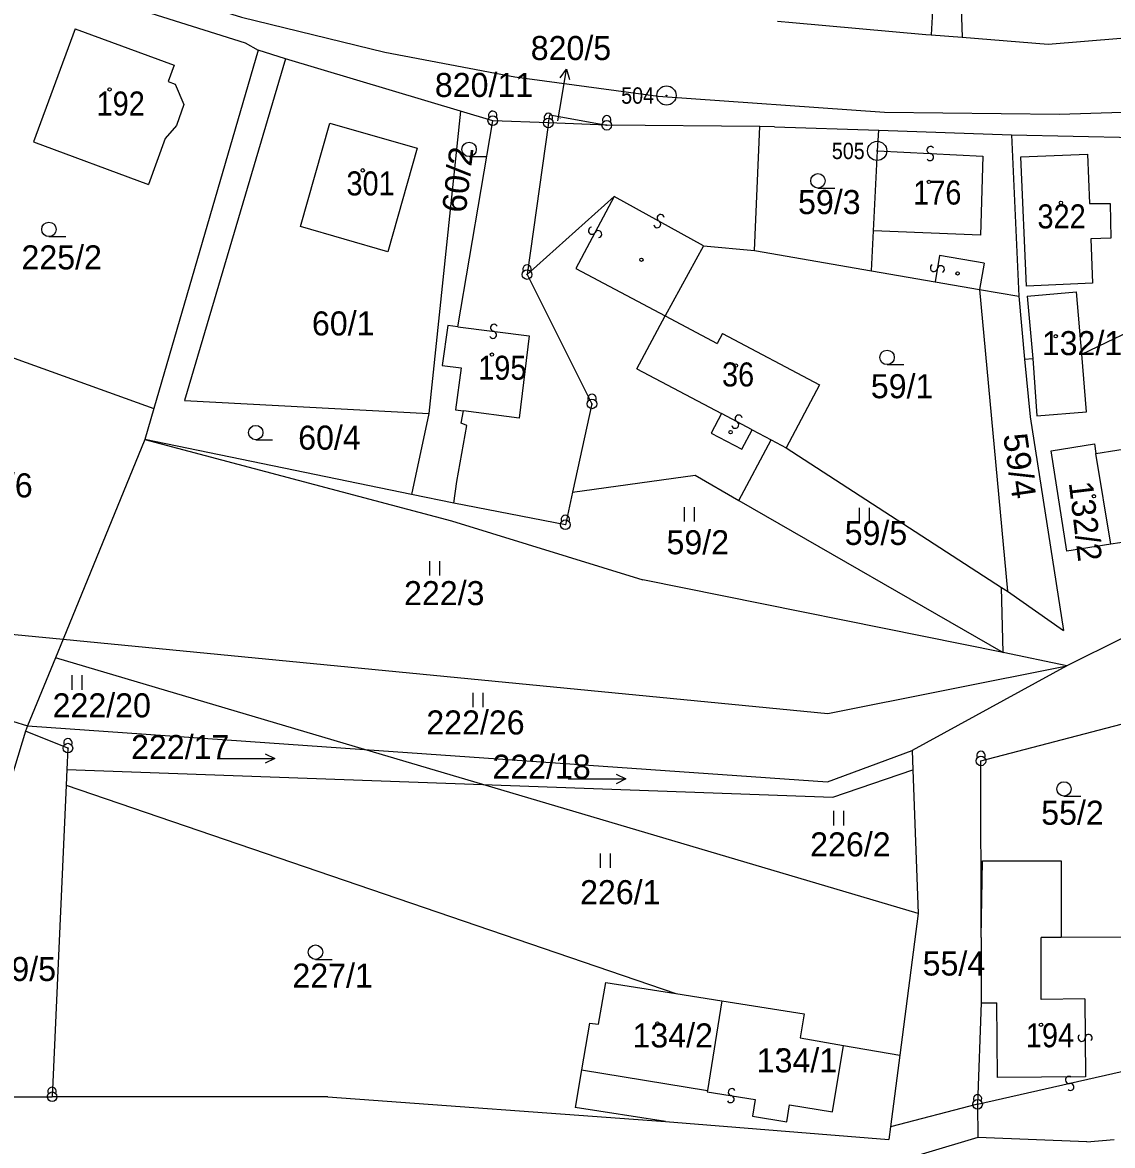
# Model space of a CAD drawing. Extents: x -680102 to -677253, y -1007548 to -1006096.
# Drawn here: x -679953.4 to -679840, y -1007209.6 to -1007092.8 of the extents above; entities that cross this region are included whole.
import ezdxf
from ezdxf.enums import TextEntityAlignment as Align

# ---------------------------------------------------------------- set-up
doc = ezdxf.new("R2010")
doc.units = 0
for name, color, linetype, lineweight in [('1', 7, 'Continuous', 25), ('16', 7, 'Continuous', 25), ('24', 7, 'Continuous', 25), ('25', 7, 'Continuous', 25), ('4', 7, 'Continuous', 25)]:
    doc.layers.add(name, color=color, linetype=linetype, lineweight=lineweight)
for name, color, linetype in [('17', 7, 'Continuous'), ('18', 7, 'Continuous'), ('19', 7, 'Continuous')]:
    doc.layers.add(name, color=color, linetype=linetype)

msp = doc.modelspace()

# ---------------------------------------------------------------- linework, layer by layer
at = {"layer": '1'}
for p, q in [((-679858.64, -1007090.34), (-679858.85, -1007094.13)), ((-679855.79, -1007089.38), (-679855.63, -1007094.38)), ((-679859.4, -1007094.09), (-679858.85, -1007094.13)), ((-679925.99, -1007096.64), (-679928.84, -1007095.74)), ((-679907.8, -1007102.06), (-679925.99, -1007096.64)), ((-679908.09, -1007124.48), (-679904.44, -1007103.06)), ((-679892.58, -1007103.53), (-679898.66, -1007103.29)), ((-679877.23, -1007116.56), (-679876.68, -1007103.67)), ((-679864.41, -1007106.19), (-679864.3, -1007104.05)), ((-679864.84, -1007114.51), (-679864.41, -1007106.19)), ((-679865.06, -1007118.66), (-679864.84, -1007114.51)), ((-679882.51, -1007116.07), (-679877.23, -1007116.56)), ((-679877.23, -1007116.56), (-679865.06, -1007118.66)), ((-679853.8, -1007120.61), (-679849.74, -1007121.31)), ((-679848.86, -1007121.31), (-679843.74, -1007120.86)), ((-679965.95, -1007123.53), (-679939.69, -1007132.98)), ((-679908.09, -1007124.48), (-679909.11, -1007124.34)), ((-679880.54, -1007125.2), (-679881.09, -1007126.23)), ((-679849.12, -1007127.86), (-679848.28, -1007127.79)), ((-679849.12, -1007127.86), (-679848.56, -1007133.84)), ((-679907.73, -1007134.52), (-679907.5, -1007133.24)), ((-679848.56, -1007133.84), (-679845.09, -1007156.09)), ((-679940.63, -1007136.2), (-679908.73, -1007144.68)), ((-679875.49, -1007136.24), (-679873.92, -1007137.07)), ((-679846.36, -1007137.38), (-679841.87, -1007136.68)), ((-679841.87, -1007136.68), (-679841.72, -1007137.67)), ((-679873.92, -1007137.07), (-679851.52, -1007151.59)), ((-679844.74, -1007147.82), (-679846.36, -1007137.38)), ((-679840.16, -1007147.11), (-679841.72, -1007137.67)), ((-679896.14, -1007141.7), (-679883.4, -1007139.91)), ((-679908.73, -1007144.68), (-679888.84, -1007150.8)), ((-679840.16, -1007147.11), (-679844.74, -1007147.82)), ((-679838.89, -1007156.83), (-679844.73, -1007159.74)), ((-679979.45, -1007157.58), (-679952.82, -1007166)), ((-679949.92, -1007158.91), (-679952.82, -1007166)), ((-679917.79, -1007168.44), (-679949.92, -1007158.91)), ((-679844.73, -1007159.74), (-679851.34, -1007158.37)), ((-679844.73, -1007159.74), (-679860.82, -1007168.55)), ((-679952.82, -1007166), (-679953.04, -1007166.53)), ((-679952.82, -1007166), (-679917.79, -1007168.44)), ((-679948.63, -1007168.31), (-679953.04, -1007166.53)), ((-679917.79, -1007168.44), (-679869.61, -1007171.8)), ((-679869.61, -1007171.8), (-679860.82, -1007168.55)), ((-679869.07, -1007173.41), (-679860.75, -1007170.55)), ((-679948.8, -1007172.16), (-679950.27, -1007204.57)), ((-679948.8, -1007172.16), (-679885.41, -1007193.82)), ((-679836.13, -1007187.98), (-679845.34, -1007188)), ((-679880.63, -1007194.58), (-679882.12, -1007203.93)), ((-679894.38, -1007196.9), (-679895.2, -1007201.78)), ((-679872.47, -1007198.45), (-679867.97, -1007199.23)), ((-679867.97, -1007199.23), (-679862.1, -1007200.25)), ((-679895.2, -1007201.78), (-679895.86, -1007205.7)), ((-679895.2, -1007201.78), (-679882.12, -1007203.93)), ((-679964.56, -1007204.56), (-679950.27, -1007204.57)), ((-679921.6, -1007204.59), (-679950.27, -1007204.57)), ((-679921.6, -1007204.59), (-679886.46, -1007207.15)), ((-679886.46, -1007207.15), (-679895.86, -1007205.7)), ((-679854.02, -1007205.35), (-679863.06, -1007207.69)), ((-679854.02, -1007205.35), (-679853.99, -1007208.8)), ((-679886.46, -1007207.15), (-679863.25, -1007209)), ((-679863.06, -1007207.69), (-679863.25, -1007209)), ((-679853.99, -1007208.8), (-679865.24, -1007212.16)), ((-679842.65, -1007209.24), (-679853.99, -1007208.8)), ((-679842.65, -1007209.24), (-679839.8, -1007209.02))]:
    msp.add_line(p, q, dxfattribs=at)
for points in [[(-679974.97, -1007077.43), (-679941.96, -1007088.72), (-679930.57, -1007092.28), (-679915.66, -1007095.94), (-679902.15, -1007098.5), (-679887.23, -1007100.52), (-679863.69, -1007102.17), (-679845.48, -1007102.38), (-679827.03, -1007101.79), (-679807.03, -1007099.79), (-679804.33, -1007100.05), (-679799.92, -1007101.29), (-679801.05, -1007105.4), (-679801.35, -1007106.51)], [(-679954.1, -1007087.39), (-679930.21, -1007094.96), (-679928.84, -1007095.74)], [(-679846.67, -1007095.09), (-679835.35, -1007094.16), (-679825.42, -1007094.12), (-679811.14, -1007091.68)], [(-679947.87, -1007093.49), (-679952.22, -1007105.26), (-679940.26, -1007109.68)], [(-679947.87, -1007093.49), (-679937.59, -1007097.29), (-679938.21, -1007098.97), (-679937.46, -1007099.25), (-679936.56, -1007101.39), (-679937.35, -1007103.54), (-679938.5, -1007104.91), (-679940.26, -1007109.68)], [(-679874.84, -1007092.69), (-679873.26, -1007092.83), (-679859.4, -1007094.09)], [(-679858.85, -1007094.13), (-679855.63, -1007094.38), (-679846.67, -1007095.09)], [(-679928.84, -1007095.74), (-679939.69, -1007132.98), (-679940.63, -1007136.2)], [(-679925.99, -1007096.64), (-679936.5, -1007132.14), (-679911.09, -1007133.5)], [(-679907.8, -1007102.06), (-679911.09, -1007133.5), (-679912.91, -1007141.93)], [(-679898.66, -1007103.29), (-679904.44, -1007103.06), (-679907.8, -1007102.06)], [(-679898.66, -1007103.29), (-679898.49, -1007102.45), (-679892.58, -1007103.53)], [(-679898.66, -1007103.29), (-679900.88, -1007119.06), (-679894.12, -1007132.51)], [(-679875.14, -1007103.68), (-679876.68, -1007103.67), (-679892.58, -1007103.53)], [(-679875.14, -1007103.68), (-679864.3, -1007104.05), (-679850.5, -1007104.53)], [(-679850.5, -1007104.53), (-679849.74, -1007121.31), (-679849.12, -1007127.86)], [(-679850.5, -1007104.53), (-679837.67, -1007104.82), (-679832.79, -1007105.1)], [(-679882.51, -1007116.07), (-679886.52, -1007123.35), (-679881.09, -1007126.23)], [(-679865.06, -1007118.66), (-679858.43, -1007119.81), (-679853.8, -1007120.61)], [(-679853.8, -1007120.61), (-679850.91, -1007151.99), (-679845.09, -1007156.09)], [(-679848.86, -1007121.31), (-679848.28, -1007127.79), (-679847.85, -1007133.75), (-679842.68, -1007133.32)], [(-679842.68, -1007133.32), (-679843.19, -1007127.35), (-679843.74, -1007120.86)], [(-679843.19, -1007127.35), (-679839.76, -1007125.71), (-679836.14, -1007123.99), (-679833.05, -1007123.53), (-679830.71, -1007123.18)], [(-679909.11, -1007124.34), (-679909.71, -1007128.51), (-679907.73, -1007128.77), (-679908.3, -1007133.13), (-679907.5, -1007133.24)], [(-679880.54, -1007125.2), (-679870.47, -1007130.53), (-679873.92, -1007137.07)], [(-679894.12, -1007132.51), (-679896.14, -1007141.7), (-679896.89, -1007145.08)], [(-679908.48, -1007142.83), (-679908.18, -1007140.57), (-679907.14, -1007134.75), (-679907.73, -1007134.52)], [(-679940.63, -1007136.2), (-679949.13, -1007156.98), (-679949.92, -1007158.91)], [(-679896.89, -1007145.08), (-679908.48, -1007142.83), (-679912.91, -1007141.93), (-679940.63, -1007136.2)], [(-679883.4, -1007139.91), (-679878.86, -1007142.54), (-679875.49, -1007136.24)], [(-679878.86, -1007142.54), (-679851.34, -1007158.37), (-679888.84, -1007150.8)], [(-679976.19, -1007149.36), (-679958.13, -1007156.11), (-679949.13, -1007156.98)], [(-679851.34, -1007158.37), (-679851.52, -1007151.59), (-679850.91, -1007151.99)], [(-679949.13, -1007156.98), (-679869.58, -1007164.72), (-679844.73, -1007159.74)], [(-679853.64, -1007188.02), (-679853.67, -1007169.64), (-679838.3, -1007165.62)], [(-679953.04, -1007166.53), (-679954.19, -1007170.32), (-679964.56, -1007204.56)], [(-679948.63, -1007168.31), (-679948.73, -1007170.52), (-679948.8, -1007172.16)], [(-679860.2, -1007185.52), (-679905.49, -1007172.09), (-679917.79, -1007168.44)], [(-679860.82, -1007168.55), (-679860.75, -1007170.55), (-679860.2, -1007185.52)], [(-679948.73, -1007170.52), (-679905.49, -1007172.09), (-679869.07, -1007173.41)], [(-679853.64, -1007188.02), (-679853.5, -1007180.02), (-679845.33, -1007180.04), (-679845.34, -1007188)], [(-679860.2, -1007185.52), (-679862.1, -1007200.25), (-679863.06, -1007207.69)], [(-679853.64, -1007188.02), (-679853.63, -1007194.81), (-679854.02, -1007205.35)], [(-679894.38, -1007196.9), (-679893.44, -1007197.02), (-679892.68, -1007192.67), (-679885.41, -1007193.82), (-679880.63, -1007194.58), (-679872.07, -1007195.94), (-679872.47, -1007198.45)]]:
    msp.add_lwpolyline(points, dxfattribs=at)
for points in [[(-679921.37, -1007103.32), (-679912.3, -1007105.93), (-679915.37, -1007116.68), (-679924.43, -1007114.07)], [(-679849.52, -1007106.82), (-679842.59, -1007106.54), (-679842.38, -1007111.66), (-679840.24, -1007111.67), (-679840.17, -1007115.27), (-679842.24, -1007115.36), (-679842.05, -1007119.97), (-679848.94, -1007120.25)]]:
    msp.add_lwpolyline(points, close=True, dxfattribs=at)
at = {"layer": '16'}
for p, q in [((-679897.27, -1007100.65), (-679896.77, -1007097.693)), ((-679897.67, -1007103.06), (-679897.27, -1007100.65))]:
    msp.add_line(p, q, dxfattribs=at)
msp.add_lwpolyline([(-679897.429, -1007098.595), (-679896.77, -1007097.693), (-679896.444, -1007098.762)], dxfattribs=at)
at = {"layer": '24'}
for centre, radius in [((-679886.37, -1007100.44), 1), ((-679886.37, -1007100.44), 0.032), ((-679904.44, -1007103.06), 0.5), ((-679904.44, -1007103.06), 0.022), ((-679898.66, -1007103.29), 0.5), ((-679892.58, -1007103.53), 0.5), ((-679898.66, -1007103.29), 0.022), ((-679892.58, -1007103.53), 0.022), ((-679864.46, -1007106.2), 1), ((-679864.46, -1007106.2), 0.032), ((-679900.88, -1007119.06), 0.5), ((-679900.88, -1007119.06), 0.022), ((-679894.12, -1007132.51), 0.5), ((-679894.12, -1007132.51), 0.022), ((-679896.89, -1007145.08), 0.5), ((-679896.89, -1007145.08), 0.022), ((-679948.63, -1007168.31), 0.5), ((-679948.63, -1007168.31), 0.022), ((-679853.67, -1007169.64), 0.5), ((-679853.67, -1007169.64), 0.022), ((-679950.27, -1007204.57), 0.5), ((-679950.27, -1007204.57), 0.022), ((-679854.02, -1007205.35), 0.5), ((-679854.02, -1007205.35), 0.022)]:
    msp.add_circle(centre, radius, dxfattribs=at)
for centre in [(-679904.441, -1007102.497), (-679898.661, -1007102.727), (-679892.581, -1007102.967), (-679900.881, -1007118.497), (-679894.121, -1007131.947), (-679896.891, -1007144.517), (-679948.631, -1007167.747), (-679853.671, -1007169.077), (-679950.271, -1007204.007), (-679854.021, -1007204.787)]:
    msp.add_arc(centre, 0.437, 328.35109, 209.97456, dxfattribs=at)
at = {"layer": '25'}
for p, q in [((-679906.9, -1007106.79), (-679905.15, -1007106.79)), ((-679870.62, -1007110.06), (-679868.87, -1007110.06)), ((-679950.6, -1007115.11), (-679948.85, -1007115.11)), ((-679863.43, -1007128.42), (-679861.68, -1007128.42)), ((-679929.09, -1007136.24), (-679927.34, -1007136.24)), ((-679884.497, -1007144.745), (-679884.497, -1007143.245)), ((-679883.463, -1007144.745), (-679883.463, -1007143.245)), ((-679866.307, -1007144.835), (-679866.307, -1007143.335)), ((-679865.273, -1007144.835), (-679865.273, -1007143.335)), ((-679910.987, -1007150.355), (-679910.987, -1007148.855)), ((-679909.953, -1007150.355), (-679909.953, -1007148.855)), ((-679948.187, -1007162.235), (-679948.187, -1007160.735)), ((-679947.153, -1007162.235), (-679947.153, -1007160.735)), ((-679906.467, -1007164.045), (-679906.467, -1007162.545)), ((-679905.433, -1007164.045), (-679905.433, -1007162.545)), ((-679933.12, -1007169.39), (-679927.12, -1007169.39)), ((-679896.61, -1007171.52), (-679890.61, -1007171.52)), ((-679845.03, -1007173.3), (-679843.28, -1007173.3)), ((-679868.957, -1007176.345), (-679868.957, -1007174.845)), ((-679867.923, -1007176.345), (-679867.923, -1007174.845)), ((-679893.237, -1007180.775), (-679893.237, -1007179.275)), ((-679892.203, -1007180.775), (-679892.203, -1007179.275)), ((-679922.88, -1007190.28), (-679921.13, -1007190.28))]:
    msp.add_line(p, q, dxfattribs=at)
for points in [[(-679928.12, -1007168.89), (-679927.12, -1007169.39), (-679928.12, -1007169.89)], [(-679891.61, -1007171.02), (-679890.61, -1007171.52), (-679891.61, -1007172.02)]]:
    msp.add_lwpolyline(points, dxfattribs=at)
for centre, radius in [((-679944.29, -1007099.81), 0.175), ((-679906.9, -1007106.04), 0.75), ((-679917.96, -1007108.22), 0.175), ((-679870.62, -1007109.31), 0.75), ((-679859.08, -1007109.42), 0.175), ((-679845.35, -1007111.6), 0.175), ((-679950.6, -1007114.36), 0.75), ((-679888.98, -1007117.52), 0.175), ((-679856.09, -1007118.94), 0.175), ((-679845.89, -1007125.47), 0.175), ((-679904.53, -1007127.38), 0.175), ((-679863.43, -1007127.67), 0.75), ((-679879.16, -1007128.53), 0.175), ((-679929.09, -1007135.49), 0.75), ((-679879.71, -1007135.45), 0.175), ((-679841.92, -1007142.12), 0.175), ((-679845.03, -1007172.55), 0.75), ((-679922.88, -1007189.53), 0.75), ((-679887.32, -1007196.94), 0.175), ((-679847.42, -1007197.08), 0.175), ((-679874.54, -1007199.71), 0.175)]:
    msp.add_circle(centre, radius, dxfattribs=at)
for centre, radius, start, end in [((-679858.918, -1007106.103), 0.367, 34.40789, 266.5716), ((-679858.963, -1007106.838), 0.368, 214.38205, 86.28931), ((-679887.34, -1007113.82), 0.367, 188.24306, 60.64273), ((-679886.978, -1007113.179), 0.369, 8.26198, 240.29235), ((-679894.123, -1007114.503), 0.369, 99.36098, 331.11888), ((-679893.477, -1007114.855), 0.367, 278.97836, 151.55256), ((-679858.563, -1007118.377), 0.368, 118.16485, 349.76614), ((-679857.838, -1007118.502), 0.367, 297.73259, 170.28256), ((-679904.411, -1007125.325), 0.368, 209.97812, 81.89314), ((-679904.31, -1007124.596), 0.367, 30.06781, 262.18073), ((-679879.224, -1007134.684), 0.368, 189.51909, 61.76304), ((-679878.874, -1007134.036), 0.368, 9.53917, 241.49068), ((-679843.198, -1007198.438), 0.368, 127.83508, 359.69147), ((-679842.463, -1007198.44), 0.367, 307.65619, 180.00143), ((-679844.518, -1007202.821), 0.368, 50.11747, 282.26039), ((-679844.363, -1007203.54), 0.368, 230.05714, 102.07669), ((-679879.703, -1007204.813), 0.369, 208.37618, 80.38474), ((-679879.58, -1007204.088), 0.367, 28.12072, 260.59109)]:
    msp.add_arc(centre, radius, start, end, dxfattribs=at)
at = {"layer": '4'}
for p, q in [((-679891.81, -1007110.93), (-679900.88, -1007119.06)), ((-679857.98, -1007117.06), (-679858.43, -1007119.81)), ((-679853.33, -1007117.86), (-679857.98, -1007117.06)), ((-679853.33, -1007117.86), (-679853.8, -1007120.61)), ((-679895.79, -1007118.43), (-679886.52, -1007123.35)), ((-679889.44, -1007128.88), (-679886.52, -1007123.35)), ((-679877.46, -1007135.2), (-679880.64, -1007133.52)), ((-679878.53, -1007137.23), (-679877.46, -1007135.2)), ((-679877.46, -1007135.2), (-679875.49, -1007136.24)), ((-679841.72, -1007137.67), (-679828.21, -1007135.56)), ((-679825.65, -1007144.85), (-679840.16, -1007147.11)), ((-679847.41, -1007194.46), (-679847.4, -1007188)), ((-679845.34, -1007188), (-679847.4, -1007188)), ((-679853.63, -1007194.81), (-679852, -1007194.8)), ((-679842.87, -1007194.4), (-679847.41, -1007194.46)), ((-679854.02, -1007205.35), (-679834.87, -1007201)), ((-679882.12, -1007203.93), (-679882.14, -1007204.05))]:
    msp.add_line(p, q, dxfattribs=at)
for points in [[(-679864.41, -1007106.19), (-679853.48, -1007106.75), (-679853.71, -1007114.95), (-679864.84, -1007114.51)], [(-679882.51, -1007116.07), (-679891.81, -1007110.93), (-679895.79, -1007118.43)], [(-679908.09, -1007124.48), (-679900.64, -1007125.44), (-679901.71, -1007133.98), (-679907.5, -1007133.24)], [(-679889.44, -1007128.88), (-679880.64, -1007133.52), (-679881.71, -1007135.56), (-679878.53, -1007137.23)], [(-679842.87, -1007194.4), (-679842.8, -1007202.48), (-679851.93, -1007202.56), (-679852, -1007194.8)], [(-679882.14, -1007204.05), (-679877.14, -1007204.85), (-679877.42, -1007206.6), (-679873.86, -1007207.17), (-679873.59, -1007205.42), (-679869.11, -1007206.13), (-679867.97, -1007199.23)]]:
    msp.add_lwpolyline(points, dxfattribs=at)

# ---------------------------------------------------------------- texts
at = {"layer": '16'}
msp.add_text('820/5', height=2.5, dxfattribs=at).set_placement((-679896.309, -1007096.75), align=Align.CENTER)
at = {"layer": '17', "width": 0.9}
for s, p in [('504', (-679887.67, -1007101.29)), ('505', (-679865.76, -1007107.05))]:
    msp.add_text(s, height=1.7, dxfattribs=at).set_placement(p, align=Align.RIGHT)
at = {"layer": '18'}
for s, height, p in [('820/11', 2.5, (-679905.35, -1007100.59)), ('820/5', 0.1, (-679897.47, -1007102.86)), ('222/26', 2.5, (-679906.24, -1007166.89))]:
    msp.add_text(s, height=height, dxfattribs=at).set_placement(p, align=Align.CENTER)
at = {"layer": '18', "width": 1.05}
for s, rotation, p in [('60/2', 83.101, (-679907.254, -1007112.728)), ('59/4', 278.302, (-679851.364, -1007135.749))]:
    msp.add_text(s, height=2.5, rotation=rotation, dxfattribs=at).set_placement(p)
at = {"layer": '18'}
for s, p in [('59/3', (-679872.69, -1007112.77)), ('225/2', (-679953.46, -1007118.52)), ('60/1', (-679923.25, -1007125.39)), ('59/1', (-679865.12, -1007131.92)), ('60/4', (-679924.68, -1007137.27)), ('222/6', (-679960.66, -1007142.23)), ('59/5', (-679867.84, -1007147.18)), ('59/2', (-679886.37, -1007148.15)), ('222/3', (-679913.67, -1007153.44)), ('222/20', (-679950.22, -1007165.11)), ('222/17', (-679942.06, -1007169.45)), ('222/18', (-679904.48, -1007171.49)), ('55/2', (-679847.4, -1007176.28)), ('226/2', (-679871.43, -1007179.57)), ('226/1', (-679895.36, -1007184.54)), ('55/4', (-679859.73, -1007191.96)), ('239/5', (-679958.23, -1007192.53)), ('227/1', (-679925.28, -1007193.22))]:
    msp.add_text(s, height=2.5, dxfattribs=at).set_placement(p)
at = {"layer": '19', "width": 0.9}
for s, p in [('192', (-679945.65, -1007102.52)), ('301', (-679919.66, -1007110.83)), ('176', (-679860.72, -1007111.78)), ('195', (-679905.96, -1007130)), ('36', (-679880.6, -1007130.7)), ('194', (-679849, -1007199.42))]:
    msp.add_text(s, height=2.5, dxfattribs=at).set_placement(p)
msp.add_text('322', height=2.5, dxfattribs=at).set_placement((-679845.28, -1007114.26), align=Align.CENTER)
at = {"layer": '19'}
for s, p in [('132/1', (-679847.34, -1007127.44)), ('134/2', (-679889.91, -1007199.44)), ('134/1', (-679876.99, -1007202.03))]:
    msp.add_text(s, height=2.5, dxfattribs=at).set_placement(p)
msp.add_text('132/2', height=2.5, rotation=276.902, dxfattribs=at).set_placement((-679844.538, -1007140.704))

doc.saveas('drawing.dxf')
